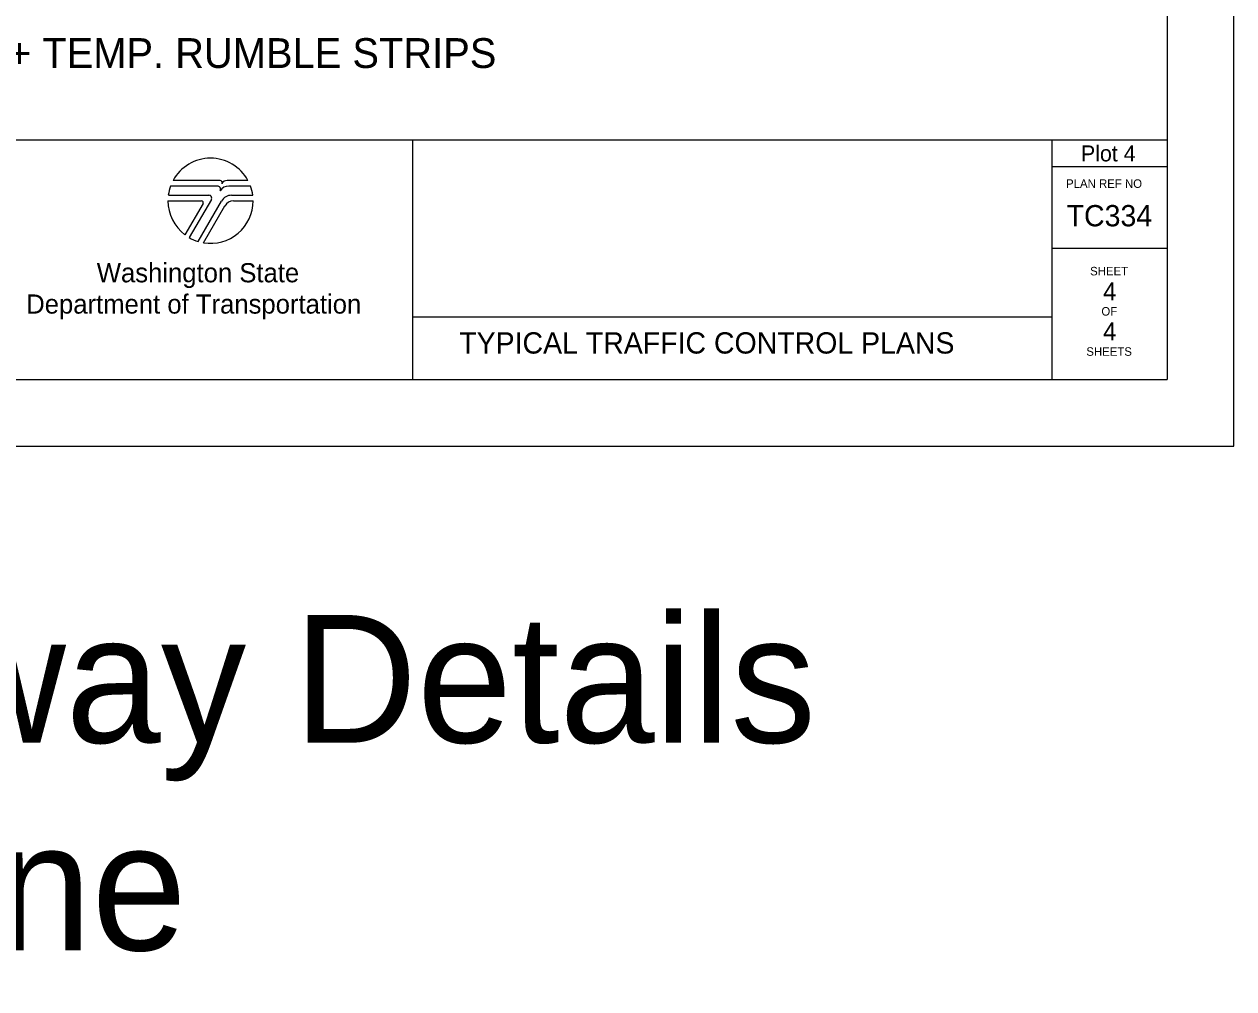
# Model space of a CAD drawing. Extents: x 99999.1 to 100095.7, y 99995 to 100010.7.
# Drawn here: x 100070.38 to 100076.06, y 99997.14 to 100001.67 of the extents above; entities that cross this region are included whole.
import ezdxf

# ---------------------------------------------------------------- set-up
doc = ezdxf.new("R2010")
doc.units = 0
for name, color, linetype in [('SH_DE_DetailHeading1Text', 7, 'Continuous'), ('SH_GI_PlotLimits', 7, 'Continuous'), ('SH_GI_SheetBorder', 7, 'Continuous'), ('SH_GI_SheetLocationText', 7, 'Continuous'), ('SH_GI_SheetTextInCells', 7, 'Continuous'), ('SH_GI_TitleBlockText', 7, 'Continuous'), ('SH_GI_WSDOTLogo', 7, 'Continuous')]:
    doc.layers.add(name, color=color, linetype=linetype)

msp = doc.modelspace()

# ---------------------------------------------------------------- linework, layer by layer
at = {"layer": 'SH_GI_PlotLimits'}
msp.add_lwpolyline([(100059.0625, 99999.6875), (100076.0625, 99999.6875), (100076.0625, 100010.6875), (100059.0625, 100010.6875)], close=True, dxfattribs=at)
at = {"layer": 'SH_GI_SheetBorder'}
for p, q in [((100075.75, 100010.375), (100075.75, 100000)), ((100060, 100001.1259), (100075.75, 100001.1259)), ((100072.2055, 100001.1259), (100072.2055, 100000)), ((100075.2079, 100001.1259), (100075.2079, 100000)), ((100075.2079, 100001.0008), (100075.75, 100001.0008)), ((100075.2079, 100000.6176), (100075.75, 100000.6176)), ((100072.2055, 100000.2955), (100075.2079, 100000.2955)), ((100060, 100000), (100075.75, 100000))]:
    msp.add_line(p, q, dxfattribs=at)
at = {"layer": 'SH_GI_WSDOTLogo'}
for p, q in [((100071.2894, 100000.9094), (100071.0697, 100000.9094)), ((100071.303, 100000.9354), (100071.0815, 100000.9354)), ((100071.433, 100000.9354), (100071.3351, 100000.9354)), ((100071.343, 100000.9094), (100071.3429, 100000.9094)), ((100071.4448, 100000.9094), (100071.343, 100000.9094)), ((100071.0572, 100000.84), (100071.2148, 100000.84)), ((100071.059, 100000.8661), (100071.2496, 100000.8661)), ((100071.222, 100000.8277), (100071.1364, 100000.6807)), ((100071.261, 100000.8464), (100071.1567, 100000.6672)), ((100071.1989, 100000.6487), (100071.3089, 100000.839)), ((100071.3558, 100000.8661), (100071.4555, 100000.8661)), ((100071.3655, 100000.8394), (100071.4572, 100000.8394)), ((100071.2244, 100000.6428), (100071.3242, 100000.8156))]:
    msp.add_line(p, q, dxfattribs=at)
for centre, radius, start, end in [((100071.2572, 100000.84), 0.2, 28.4787, 151.532), ((100071.2572, 100000.84), 0.2, 159.696, 172.5057), ((100071.2894, 100000.8946), 0.0148, 327.8418, 89.9985), ((100071.3429, 100000.861), 0.0484, 89.9953, 147.8238), ((100071.303, 100000.9263), 0.00903, 329.8742, 90.0033), ((100071.3352, 100000.9066), 0.0287, 90.0072, 148.1676), ((100071.2572, 100000.84), 0.2, 7.4943, 20.2941), ((100071.2572, 100000.84), 0.2, 179.9986, 232.8433), ((100071.2149, 100000.8318), 0.0082, 329.7436, 90), ((100071.2572, 100000.84), 0.2, 260.5455, 359.8086), ((100071.2497, 100000.853), 0.0131, 329.7683, 90), ((100071.3558, 100000.8119), 0.0542, 90, 149.9974), ((100071.3654, 100000.7918), 0.0476, 90, 150.0543), ((100071.2572, 100000.84), 0.2, 239.7929, 253.0448)]:
    msp.add_arc(centre, radius, start, end, dxfattribs=at)

# ---------------------------------------------------------------- texts
at = {"layer": 'SH_DE_DetailHeading1Text'}
msp.add_text('PILOT CAR OPERATION FOR ALTERNATING 1-LANE, 2-WAY TRAFFIC: AFAD-CONTROLLED + TEMP. RUMBLE STRIPS', height=0.14, rotation=360, dxfattribs=at).set_placement((100062.109, 100001.4639))
at = {"layer": 'SH_GI_SheetBorder'}
msp.add_text('PLAN REF NO', height=0.040032, dxfattribs=at).set_placement((100075.2747, 100000.9008))
at = {"layer": 'SH_GI_SheetLocationText'}
for s, height, p in [('Plot 4', 0.075, (100075.3447, 100001.025)), ('Access & Intersecting Roadway Details', 0.6, (100060.1422, 99998.2946)), ('Separated Bike Lane', 0.6, (100063.6511, 99997.3196))]:
    msp.add_text(s, height=height, dxfattribs=at).set_placement(p)
at = {"layer": 'SH_GI_SheetTextInCells'}
for s, height, p in [('Washington State', 0.090072, (100070.7229, 100000.4571)), ('SHEET', 0.04003, (100075.3877, 100000.4896)), ('Department of Transportation', 0.090072, (100070.3916, 100000.3101)), ('OF', 0.04003, (100075.4406, 100000.3008)), ('SHEETS', 0.04003, (100075.3698, 100000.112))]:
    msp.add_text(s, height=height, dxfattribs=at).set_placement(p)
at = {"layer": 'SH_GI_TitleBlockText'}
for s, height, p in [('TC334', 0.1, (100075.2776, 100000.72)), ('4', 0.085, (100075.4485, 100000.3723)), ('4', 0.085, (100075.4485, 100000.1843)), ('TYPICAL TRAFFIC CONTROL PLANS', 0.1, (100072.4251, 100000.1224))]:
    msp.add_text(s, height=height, dxfattribs=at).set_placement(p)

doc.saveas('drawing.dxf')
